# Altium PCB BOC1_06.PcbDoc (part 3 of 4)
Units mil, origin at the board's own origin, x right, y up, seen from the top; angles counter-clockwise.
Board outline 7900 x 6500 mil, 2 copper layers (Top Layer, Bottom Layer); 312 components, 413 nets, 1710 pads, 368 vias.
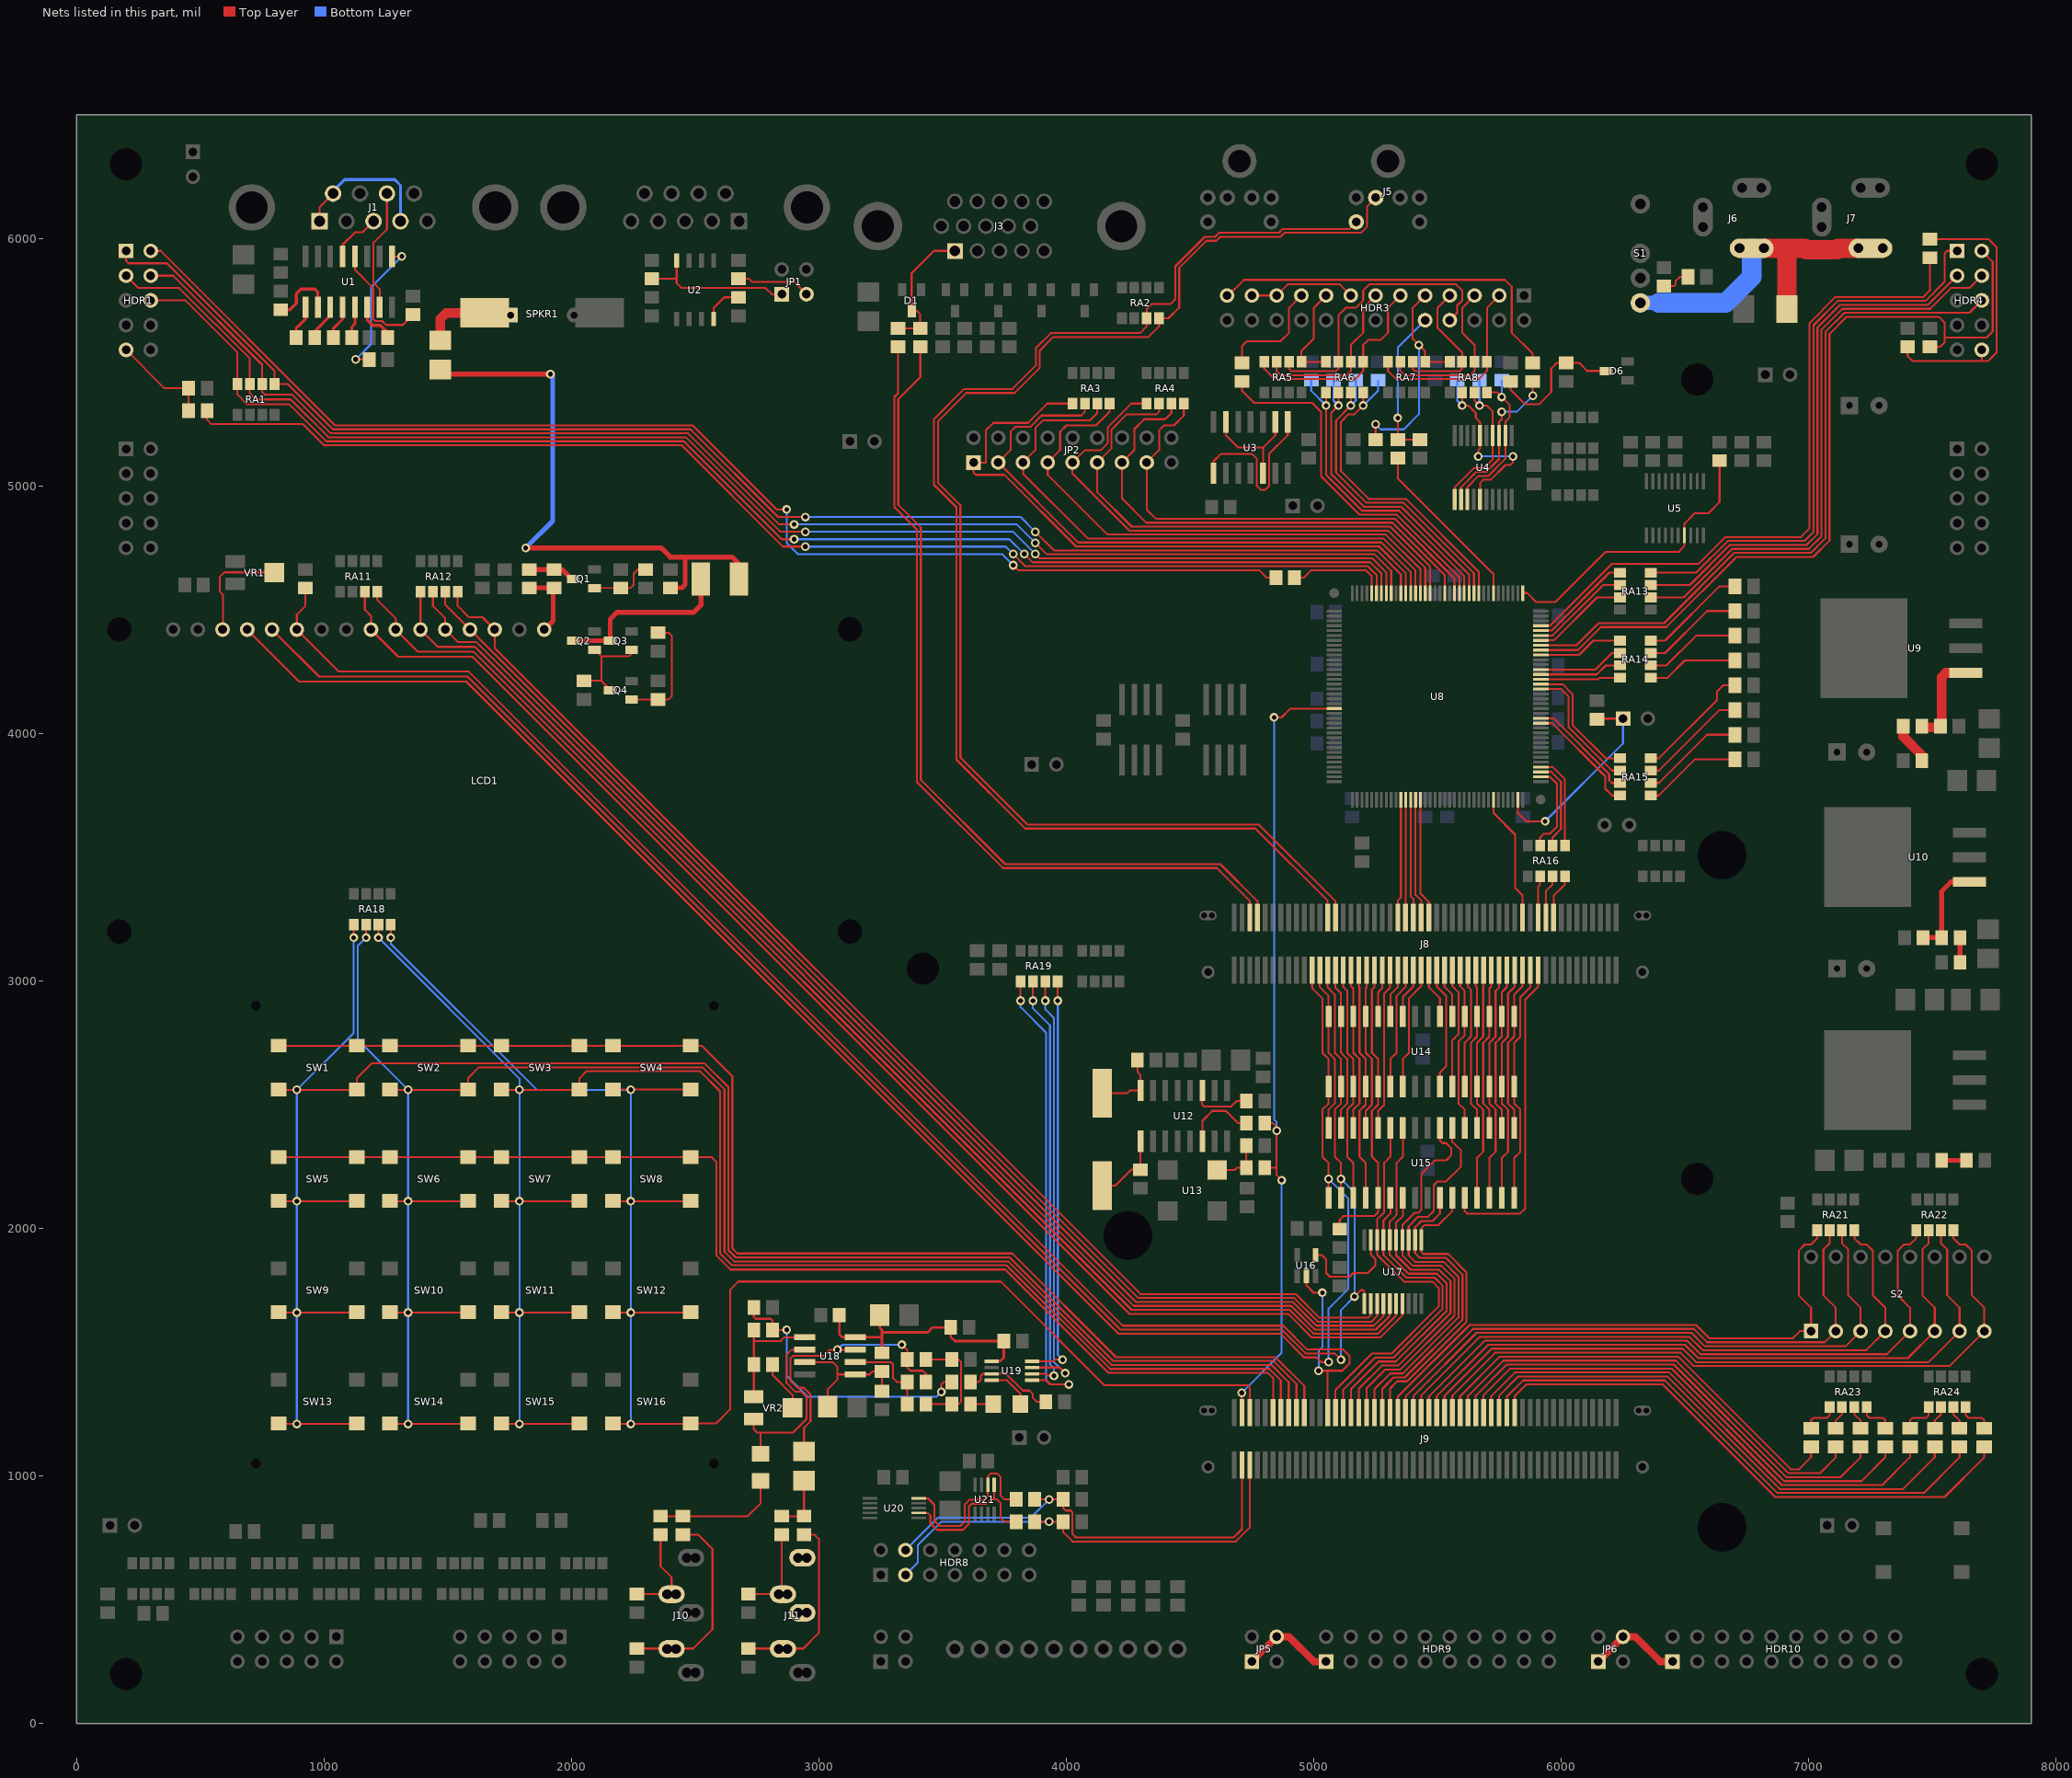
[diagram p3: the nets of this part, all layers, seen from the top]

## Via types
v1: diameter 35.43, hole 19.68, Top Layer to Bottom Layer, 194 vias
v2: diameter 35.43, hole 19.68, Top Layer to Bottom Layer, tented both sides, 169 vias
v3: diameter 50, hole 27.56, Top Layer to Bottom Layer, 5 vias

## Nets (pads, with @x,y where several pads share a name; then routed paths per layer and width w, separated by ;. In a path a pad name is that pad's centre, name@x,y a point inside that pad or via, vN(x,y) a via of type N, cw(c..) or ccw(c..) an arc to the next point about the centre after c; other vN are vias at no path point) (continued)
LCD_D2: LCD1.9 RA11.3 U17.7 | length 5601.5
  Top Layer w7.87: RA11.3@1165,4573 1165,4500 1190,4475 LCD1.9@1190,4420 1300,4310 1600,4310 4255,1655 4896.35,1655 4992.35,1559 5269,1559 5358.39,1648.39 U17.7@5358.39,1696.06
LCD_D3: LCD1.10 RA11.4 U17.6 | length 5483.7
  Top Layer w7.87: RA11.4@1215,4573 1215,4540 1290,4465 LCD1.10@1290,4420 1380,4330 1605,4330 4264,1671 4902.63,1671 4998.63,1575 5260,1575 5332.8,1647.8 U17.6@5332.8,1696.06
LCD_D4: LCD1.11 RA12.1 U17.5 | length 5314.2
  Top Layer w7.87: RA12.1@1390,4573 LCD1.11@1390,4420 1460,4350 1610,4350 4273,1687 4908.9,1687 5004.9,1591 5251,1591 5307.2,1647.2 U17.5@5307.2,1696.06
LCD_D5: LCD1.12 RA12.2 U17.4 | length 5196.4
  Top Layer w7.87: RA12.2@1440,4573 1440,4515 1490,4465 LCD1.12@1490,4420 1540,4370 1615,4370 4282,1703 4915.17,1703 5011.17,1607 5242,1607 5281.61,1646.61 U17.4@5281.61,1696.06
LCD_D6: LCD1.13 RA12.3 U17.3 | length 5078.6
  Top Layer w7.87: RA12.3@1490,4573 1490,4520 4291,1719 4921.44,1719 5017.44,1623 5233,1623 5256.02,1646.02 U17.3@5256.02,1696.06
LCD_D7: LCD1.14 RA12.4 U17.2 | length 5034.6
  Top Layer w7.87: RA12.4@1540,4573 1540,4515 1585,4470 1640,4470 LCD1.14@1690,4420 1690,4345 4300,1735 4927.71,1735 5023.71,1639 5220,1639 5230.43,1649.43 U17.2@5230.43,1696.06
LCD_E: J9.26 LCD1.6 R29.1 U16.2 | length 6425.3
  Top Layer w7.87: R29.1@925,4587.6 925,4515 890,4480 LCD1.6@890,4420 1060,4250 1585,4250 4228,1607 4877.54,1607 4973.54,1511 5119,1511 5145,1485 5145,1455 5115,1425 v2(5020,1425) ; U16.2@4970,1807.68 4970,1770 5000,1740 v1(5035,1740) ; J9.26@5056.3,1256.3 5056.3,1425
  Bottom Layer w7.87: v2(5020,1425) 5020,1505 5035,1520 v1(5035,1740)
LCD_EN: U16.4 U17.19 | length 440.3
  Top Layer w7.87: U16.4@5007.4,1892.32 5032.68,1892.32 5050,1875 5050,1820 5065,1805 5145,1805 5160,1820 5219,1820 5249,1850 5249,1876 5230.43,1894.57 U17.19@5230.43,1953.94
LED0: J9.60 LED0.1 | length 1801
  Top Layer w7.87: J9.60@5591.73,1256.3 5591.73,1321.73 5752,1482 6473,1482 6928,1027 6962,1027 7010,1075 LED0.1@7010,1117.6
LED0#: LED0.2 RA23.1 | length 148.9
  Top Layer w7.87: LED0.2@7010,1192.4 7010,1225 7020,1235 7075,1235 7085,1245 RA23.1@7085,1278
LED1: J9.62 LED1.1 | length 1870.4
  Top Layer w7.87: J9.62@5623.23,1256.3 5623.23,1323.23 5766,1466 6464,1466 6919,1011 7046,1011 7110,1075 LED1.1@7110,1117.6
LED1#: LED1.2 RA23.2 | length 96
  Top Layer w7.87: LED1.2@7110,1192.4 7110,1224 7135,1249 RA23.2@7135,1278
LED2: J9.64 LED2.1 | length 1939.8
  Top Layer w7.87: J9.64@5654.72,1256.3 5654.72,1324.72 5780,1450 6455,1450 6910,995 7130,995 7210,1075 LED2.1@7210,1117.6
LED2#: LED2.2 RA23.3 | length 96
  Top Layer w7.87: RA23.3@7185,1278 7185,1249 7210,1224 LED2.2@7210,1192.4
LED3: J9.66 LED3.1 | length 2009.2
  Top Layer w7.87: J9.66@5686.22,1256.3 5686.22,1326.22 5794,1434 6446,1434 6901,979 7214,979 7310,1075 LED3.1@7310,1117.6
LED3#: LED3.2 RA23.4 | length 148.9
  Top Layer w7.87: RA23.4@7235,1278 7235,1245 7245,1235 7300,1235 7310,1225 LED3.2@7310,1192.4
LED4: J9.68 LED4.1 | length 2075.6
  Top Layer w7.87: J9.68@5717.72,1256.3 5717.72,1322.72 5813,1418 6437,1418 6892,963 7298,963 7410,1075 LED4.1@7410,1117.6
LED4#: LED4.2 RA24.1 | length 148.9
  Top Layer w7.87: LED4.2@7410,1192.4 7410,1225 7420,1235 7475,1235 7485,1245 RA24.1@7485,1278
LED5: J9.70 LED5.1 | length 2145
  Top Layer w7.87: J9.70@5749.21,1256.3 5749.21,1324.21 5827,1402 6428,1402 6883,947 7382,947 7510,1075 LED5.1@7510,1117.6
LED5#: LED5.2 RA24.2 | length 96
  Top Layer w7.87: LED5.2@7510,1192.4 7510,1224 7535,1249 RA24.2@7535,1278
LED6: J9.72 LED6.1 | length 2211.5
  Top Layer w7.87: J9.72@5780.71,1256.3 5780.71,1320.71 5846,1386 6419,1386 6874,931 7466,931 7610,1075 LED6.1@7610,1117.6
LED6#: LED6.2 RA24.3 | length 96
  Top Layer w7.87: RA24.3@7585,1278 7585,1249 7610,1224 LED6.2@7610,1192.4
LED7: J9.74 LED7.1 | length 2280.8
  Top Layer w7.87: J9.74@5812.21,1256.3 5812.2,1322.21 5860,1370 6410,1370 6865,915 7550,915 7710,1075 LED7.1@7710,1117.6
LED7#: LED7.2 RA24.4 | length 148.9
  Top Layer w7.87: RA24.4@7635,1278 7635,1245 7645,1235 7700,1235 7710,1225 LED7.2@7710,1192.4
MASTER: R8.2 U8.103 | length 5097.2
  Top Layer w7.87: R8.2@527.4,5305 527.4,5267.6 545,5250 915,5250 1000,5165 2445,5165 2855,4755 v1(2945,4755) ; v1(3785,4725) 3834,4676 5219,4676 5253.94,4641.06 U8.103@5253.94,4567.32
  Bottom Layer w7.87: v1(2945,4755) 3755,4755 v1(3785,4725)
MASTER#: HDR1.9 R7.2 R8.1 | length 406.8
  Top Layer w7.87: HDR1.9@200,5550 355,5395 R7.2@452.6,5395 R8.1@452.6,5305
MASTER_MODE: HDR1.6 RA1.8 U8.102 | length 5609.4
  Top Layer w7.87: HDR1.6@300,5750 440,5750 650,5540 650,5370 690,5330 860,5330 1009,5181 2454,5181 2850,4785 v1(2900,4785) ; v1(3830,4725) 3863,4692 5228,4692 5273.62,4646.38 U8.102@5273.62,4567.32
  Bottom Layer w7.87: v1(2900,4785) 3770,4785 v1(3830,4725)
MASTER_TCK: HDR1.3 RA1.7 U8.101 | length 5756
  Top Layer w7.87: HDR1.3@200,5850 250,5800 415,5800 700,5515 700,5375 725,5350 865,5350 1018,5197 2463,5197 2845,4815 v1(2945,4815) ; v1(3875,4725) 3892,4708 5237,4708 5293.31,4651.69 U8.101@5293.31,4567.32
  Bottom Layer w7.87: v1(2945,4815) 3785,4815 v1(3875,4725)
MASTER_TDI: HDR1.1 RA1.5 U8.98 | length 5823.7
  Top Layer w7.87: HDR1.1@200,5950 200,5910 210,5900 365,5900 800,5465 RA1.5@800,5412 853,5412 1036,5229 2481,5229 2835,4875 v1(2945,4875) ; v1(3875,4815) 3950,4740 5255,4740 5352.36,4642.64 U8.98@5352.36,4567.32
  Bottom Layer w7.87: v1(2945,4875) 3815,4875 v1(3875,4815)
MASTER_TDO: HDR1.2 R36.1 | length 5173.4
  Top Layer w7.87: HDR1.2@300,5950 340,5950 1045,5245 2490,5245 2830,4905 v1(2870,4905) ; v1(3785,4680) 3805,4660 4780,4660 4810,4630 R36.1@4847.6,4630
  Bottom Layer w7.87: v1(2870,4905) 2870,4770 2915,4725 3740,4725 v1(3785,4680)
MASTER_TDO#: R36.2 U8.104 | length 402.7
  Top Layer w7.87: R36.2@4922.4,4630 4960,4630 4990,4660 5210,4660 5234.25,4635.75 U8.104@5234.25,4567.32
MASTER_TMS: HDR1.4 RA1.6 U8.100 | length 5661.3
  Top Layer w7.87: HDR1.4@300,5850 390,5850 750,5490 750,5380 760,5370 870,5370 1027,5213 2472,5213 2840,4845 v1(2900,4845) ; v1(3875,4770) 3921,4724 5246,4724 5312.99,4657.01 U8.100@5312.99,4567.32
  Bottom Layer w7.87: v1(2900,4845) 3800,4845 v1(3875,4770)
MODE: C85.1 RA6.4 U8.82 | length 1308.8
  Top Layer w7.87: RA6.4@5200,5378 v2(5200,5325) 5165,5290 5140,5290 5110,5260 5110,5060 5222,4948 5372,4948 5667.32,4652.68 U8.82@5667.32,4567.32
  Bottom Layer w7.87: v2(5200,5325) 5260,5385 C85.1@5260,5427.6
MODE_1: JP2.1 RA3.1 U8.97 | length 2611
  Top Layer w7.87: RA3.1@4025,5333 3923,5333 3845,5255 3705,5255 3675,5225 3675,5095 JP2.1@3625,5095 3625,5055 3635,5045 3750,5045 4039,4756 5264,4756 5372.05,4647.95 U8.97@5372.05,4567.32
MODE_2: JP2.3 RA3.2 U8.96 | length 2447.5
  Top Layer w7.87: RA3.2@4075,5333 4075,5300 4060,5285 3900,5285 3854,5239 3794,5239 3775,5220 3775,5145 JP2.3@3725,5095 4048,4772 5273,4772 5391.73,4653.27 U8.96@5391.73,4567.32
MODE_3: JP2.5 RA3.3 U8.95 | length 2358.4
  Top Layer w7.87: RA3.3@4125,5333 4125,5295 4095,5265 3905,5265 3875,5235 3875,5145 JP2.5@3825,5095 3825,5050 4087,4788 5282,4788 5411.42,4658.58 U8.95@5411.42,4567.32
MODE_4: JP2.7 RA3.4 U8.94 | length 2222.4
  Top Layer w7.87: RA3.4@4175,5333 4175,5300 4120,5245 4000,5245 3975,5220 3975,5145 JP2.7@3925,5095 3925,5045 4166,4804 5291,4804 5431.1,4663.9 U8.94@5431.1,4567.32
MODE_5: JP2.9 RA4.1 U8.93 | length 2167.1
  Top Layer w7.87: RA4.1@4325,5333 4263,5333 4167,5237 4167,5172 4140,5145 4075,5145 JP2.9@4025,5095 4025,5050 4255,4820 5300,4820 5450.79,4669.21 U8.93@5450.79,4567.32
MODE_6: JP2.11 RA4.2 U8.92 | length 2109
  Top Layer w7.87: RA4.2@4375,5333 4375,5300 4365,5290 4245,5290 4183,5228 4183,5153 JP2.11@4125,5095 4125,4975 4264,4836 5309,4836 5470.47,4674.53 U8.92@5470.47,4567.32
MODE_7: JP2.13 RA4.3 U8.89 | length 2021.5
  Top Layer w7.87: RA4.3@4425,5333 4425,5295 4400,5270 4315,5270 4275,5230 4275,5145 JP2.13@4225,5095 4225,4950 4323,4852 5318,4852 5529.53,4640.47 U8.89@5529.53,4567.32
MODE_8: JP2.15 RA4.4 U8.87 | length 1931.8
  Top Layer w7.87: RA4.4@4475,5333 4475,5285 4435,5245 4395,5245 4375,5225 4375,5145 JP2.15@4325,5095 4325,4905 4362,4868 5327,4868 5568.9,4626.1 U8.87@5568.9,4567.32
MOUSECLOCK: J5.5 J8.26 RA2.3 | length 5414.9
  Top Layer w7.87: J8.26@5056.3,3256.3 5056.3,3323.7 4764,3616 3834,3616 3556,3894 3556,4914 3465,5005 3465,5270 3587,5392 3782,5392 3877,5487 3877,5557 3938,5618 4298,5618 4325,5645 RA2.3@4325,5678 4325,5715 4345.07,5735.07 4421.07,5735.07 4440.5,5754.5 4440.5,5887.84 4559.66,6007 4600.27,6007 4616.27,6023 4859,6023 4874.75,6038.75 5143.87,6038.75 J5.5@5172.05,6066.93
MOUSEDATA: J5.1 J8.28 RA2.4 | length 5564.2
  Top Layer w7.87: J8.28@5087.79,3256.3 5087.79,3322.21 4778,3632 3843,3632 3572,3903 3572,4923 3481,5014 3481,5261 3596,5376 3791,5376 3893,5478 3893,5548 3947,5602 4332,5602 4375,5645 RA2.4@4375,5678 4413,5678 4456.24,5721.24 4456.24,5881.31 4565.93,5991 4606.54,5991 4622.54,6007 4865.27,6007 4881.27,6023 5190,6023 5216,6049 5216,6130.57 J5.1@5250.79,6165.35
N_TCK: C88.1 RA6.1 U8.85 | length 1257.2
  Top Layer w7.87: RA6.1@5050,5378 5050,5045 5195,4900 5345,4900 5608.27,4636.73 U8.85@5608.27,4567.32
  Bottom Layer w7.87: C88.1@4990,5427.6 4990,5385 v2(5050,5325)
N_TDI: C86.1 RA6.3 U8.83 | length 1265.3
  Top Layer w7.87: RA6.3@5150,5378 v2(5150,5325) 5090,5265 5090,5055 5213,4932 5363,4932 5647.64,4647.36 U8.83@5647.64,4567.32
  Bottom Layer w7.87: v2(5150,5325) 5170,5345 C86.1@5170,5427.6
N_TDO: R16.2 U8.86 | length 1444.7
  Top Layer w7.87: R16.2@4710,5422.6 4710,5385 4759,5336 4994,5336 5030,5300 5030,5040 5186,4884 5336,4884 5588.58,4631.42 U8.86@5588.58,4567.32
N_TDO#: HDR3.10 R16.1 | length 451.1
  Top Layer w7.87: R16.1@4710,5497.4 4710,5565 4730,5585 4865,5585 4900,5620 4900,5720 HDR3.10@4950,5770
N_TMS: C87.1 RA6.2 U8.84 | length 1253
  Top Layer w7.87: RA6.2@5100,5378 v2(5100,5325) 5070,5295 5070,5050 5204,4916 5354,4916 5627.95,4642.05 U8.84@5627.95,4567.32
  Bottom Layer w7.87: C87.1@5080,5427.6 5080,5345 v2(5100,5325)
N_TMS#: HDR3.17 RA5.6 RA6.7 | length 1178.6
  Top Layer w7.87: RA5.6@4900,5502 4900,5474 4910,5464 5090,5464 5100,5474 5100,5690 5130,5720 5170,5720 5200,5750 5200,5790 5225,5815 5575,5815 5600,5790 5600,5750 5580,5730 5580,5700 HDR3.17@5550,5670
NetC3_2: C3.2 U1.2 | length 273.6
  Top Layer w11.81: C3.2@825.1,5712.6 862.6,5712.6 888,5738 888,5777 907,5796 963,5796 975,5784 U1.2@975,5722.64
NetC6_1: C6.1 U1.1 | length 138.1
  Top Layer w11.81: C6.1@887.6,5600 887.6,5637.6 925,5675 U1.1@925,5722.64
NetC6_2: C6.2 U1.3 | length 148.6
  Top Layer w11.81: C6.2@962.4,5600 962.4,5625.1 1025,5687.7 U1.3@1025,5722.64
NetC7_1: C7.1 U1.4 | length 138.1
  Top Layer w11.81: C7.1@1037.6,5600 1037.6,5636.6 1075,5674 U1.4@1075,5722.64
NetC7_2: C7.2 U1.5 | length 127.9
  Top Layer w11.81: C7.2@1112.4,5600 1112.4,5642.4 1125,5655 U1.5@1125,5722.64
NetC8_1: C8.1 U1.6 | length 174.9
  Top Layer w11.81: U1.6@1175,5722.64 1175,5671 1197,5649 1227.95,5649 1257.4,5619.54 C8.1@1257.4,5600
NetC9_1: C9.1 C18.1 L1.2 | length 2315.7
  Top Layer w19.68: C9.1@1470,5470.95 1488.94,5452 v2(1915,5452) ; v2@1815.57,4750 2362.57,4750 2399.57,4713 2648.57,4713 2678.35,4683.23 L1.2@2678.35,4626.57 ; C18.1@2401.48,4588.6 2446.17,4588.6 2459.57,4602 2459.57,4703
  Bottom Layer w19.68: v2@1815.57,4750 1924.6,4859.02 1924.6,5442.4 v2(1915,5452)
  other v2: 1815,4750
NetC9_2: C9.2 SPKR1.1 SPKR1.1A | length 276.6
  Top Layer w39.37: C9.2@1470,5589.06 1470,5675 1494,5700 SPKR1.1@1650,5700
NetC28_1: C28.1 CR1.1 U12.16 | length 287.1
  Top Layer w7.87: CR1.1@4145,2547.01 4247.01,2547.01 4257.36,2557.36 U12.16@4300,2557.36 4300,2620 4287.6,2632.4 C28.1@4287.6,2680
NetC31_1: C31.1 CR1.2 U12.1 | length 296.9
  Top Layer w7.87: CR1.2@4145,2172.99 4197.99,2172.99 4262.4,2237.4 C31.1@4300,2237.4 U12.1@4300,2352.64
NetC36_1: C36.1 R60.2 R67.1 | length 1144
  Top Layer w7.87: C36.1@2737.6,1680 2737.6,1642.4 2745,1635 2805,1635 2812.4,1627.6 R60.2@2812.4,1590 v1(2870,1590) ; v1(3495,1340) 3495,1370 3505,1380 R67.1@3537.6,1380
  Bottom Layer w7.87: v1(2870,1590) 2870,1405 2955,1320 3475,1320 v1(3495,1340)
NetC37_2: C37.2 C38.1 C42.1 R61.2 R63.2 U18.8 U19.1 | length 1079.8
  Top Layer w9.84: C37.2@3082.4,1650 3082.4,1572.6 3095,1560 3255,1560 ; C38.1@3245.95,1650 3245.95,1599.05 3255,1590 R63.2@3255,1497.4 ; 3255,1580 3440,1580 3460,1600 R61.2@3532.6,1600 3532.6,1562.4 3550,1545 C42.1@3747.6,1545 3747.6,1477.6 3733.39,1463.39 U19.1@3698.31,1463.39
NetC39_1: C39.1 R63.1 R65.2 U18.3 U18.5 | length 582.2
  Top Layer w7.87: U18.3@2942.64,1460 3055,1460 3075,1440 3075,1390 3035.95,1350.95 C39.1@3035.95,1280 ; 3075,1410 3205,1410 3217.6,1422.6 R63.1@3255,1422.6 R65.2@3255,1342.4
NetC40_1: C40.1 R66.2 U18.6 | length 365.6
  Top Layer w7.87: U18.6@3147.36,1460 3290,1460 3300,1450 3300,1395 3315,1380 C40.1@3357.6,1380 R66.2@3357.6,1290
NetC40_2: C40.2 C46.1 R64.1 U18.7 | length 1199.7
  Top Layer w7.87: C46.1@2940,1099.05 2940,1195 2966,1221 2966,1329 2939,1356 2914,1356 2885,1385 2885,1475 2895,1485 3020,1485 3045,1510 U18.7@3147.36,1510 ; v1(3335,1530) 3357.6,1507.4 3357.6,1437.4 3370,1425 3420,1425 3432.4,1412.6 C40.2@3432.4,1380
  Bottom Layer w7.87: v1(3075,1510) 3095,1530 v1(3335,1530)
NetC41_1: C41.1 R64.2 R66.1 R68.1 | length 453.5
  Top Layer w7.87: R66.1@3432.4,1290 3565,1290 3575,1300 3575,1460 3565,1470 R64.2@3432.4,1470
NetC43_1: C43.1 R68.2 | length 92.5
  Top Layer w7.87: R68.2@3612.4,1290 C43.1@3704.88,1290
NetC43_2: C43.2 U19.4 | length 180.8
  Top Layer w7.87: U19.4@3698.31,1386.61 3759.39,1386.61 3815.12,1330.88 C43.2@3815.12,1290
NetC44_1: C44.1 R67.2 U19.3 | length 382.6
  Top Layer w7.87: R67.2@3612.4,1380 3645,1380 3655,1390 3655,1405 3662.2,1412.2 3756.8,1412.2 3824,1345 3850,1345 3865,1330 3865,1315 3880,1300 C44.1@3917.6,1300
NetC45_1: C45.1 R71.2 R72.2 | length 516.7
  Top Layer w7.87: R71.2@2360,837.4 2712.4,837.4 2765,890 C45.1@2765,979.88
NetC45_2: C45.2 U18.2 VR2.CCW | length 757.6
  Top Layer w7.87: VR2.CCW@2736.26,1229.72 2736.26,1188.74 2750,1175 2895,1175 2950,1230 2950,1320 2930,1340 2905,1340 2869,1376 2869,1489 2890,1510 U18.2@2942.64,1510 ; C45.2@2765,1090.12 2765,1175
NetC46_2: C46.2 R73.2 R74.2 | length 233.5
  Top Layer w7.87: R73.2@2850,837.4 R74.2@2940,837.4 C46.2@2940,980.94
NetC50_1: C50.1 J10.4 J10.4A J10.4B R71.1 | length 398.4
  Top Layer w7.87: C50.1@2265,522.4 2404.72,522.4 2404.72,590.28 2360,635 R71.1@2360,762.6
NetC51_1: C51.1 J10.2 J10.2A J10.2B R72.1 | length 806.1
  Top Layer w7.87: C51.1@2265,302.4 2492.6,302.4 2570,380 2570,705 2512.4,762.6 R72.1@2450,762.6
NetC52_1: C52.1 J11.4 J11.4A J11.4B R73.1 | length 375.2
  Top Layer w7.87: C52.1@2715,522.4 2850,522.4 R73.1@2850,762.6
NetC53_1: C53.1 J11.2 J11.2A J11.2B R74.1 | length 758.2
  Top Layer w7.87: C53.1@2715,302.4 2937.4,302.4 3000,365 3000,745 2982.4,762.6 R74.1@2940,762.6
NetD6_3: D6.3 R17.2 R19.1 | length 582.6
  Top Layer w7.87: R17.2@5795,5422.6 5795,5390 5855,5330 5910,5330 5960,5380 5960,5475 5982.4,5497.4 6072.6,5497.4 6105,5465 D6.3@6181.69,5465
NetJ1_1: J1.1 J1.4 J1.6 | length 590.3
  Top Layer w7.87: J1.1@981.89,6070.08 981.89,6127.36 J1.6@1036.42,6181.89
  Bottom Layer w11.81: J1.6@1036.42,6181.89 1036.42,6191.42 1083,6238 1286,6238 1309.05,6214.95 J1.4@1309.05,6070.08
NetJ11_3: J11.3 J11.3A J11.3B
NetJ11_5: J11.5 J11.5A J11.5B
NetJP1_1: JP1.1 R2.2 U2.8 | length 634.9
  Top Layer w7.87: R2.2@2325,5837.6 2425,5837.6 ; U2.8@2425,5911.22 2425,5820 2445,5800 2785,5800 2810,5775 JP1.1@2850,5775
NetJP1_3: JP1.3 R3.1 | length 300.9
  Top Layer w7.87: R3.1@2675,5837.6 2717.4,5837.6 2730,5825 2900,5825 JP1.3@2950,5775
NetL1_1: L1.1 Q2.3 Q3.3 | length 733.4
  Top Layer w19.68: Q2.3@2006.69,4375 Q3.3@2156.69,4375 2156.69,4461.69 2185,4490 2495,4490 2523.23,4518.23 L1.1@2523.23,4625
NetLCD1_3: LCD1.3 VR1.W | length 446.8
  Top Layer w7.87: LCD1.3@591.53,4419.9 591.53,4561 578.23,4574.31 578.23,4632.65 596.85,4651.28 VR1.W@799.06,4651.28
NetLCD1_16: LCD1.16 R32.1 R33.1 | length 283.2
  Top Layer w19.68: R32.1@1826.47,4588.6 1926.47,4588.6 1926.47,4454.84 LCD1.16@1891.54,4419.9
NetLED8_1: LED8.1 R5.2 | length 120.7
  Top Layer w7.87: R5.2@6415,5807.6 6455.6,5807.6 6462,5814 6462,5827 6480,5845 LED8.1@6512.6,5845
NetQ1_1: Q1.1 R34.2 R35.2 | length 265.5
  Top Layer w7.87: Q1.1@2093.31,4587.6 2239.17,4588.6 2251.57,4601 2251.57,4646 2268.97,4663.4 R35.2@2301.48,4663.4
NetQ1_3: Q1.3 R32.2 R33.2 | length 184.1
  Top Layer w19.68: R32.2@1830,4662.4 R33.2@1930,4662.4 1961.17,4663.4 Q1.3@1998.57,4626
NetQ2_1: Q2.1 Q3.1 Q4.3 R38.2 | length 387.1
  Top Layer w7.87: R38.2@2051.47,4213.4 2120.87,4213.4 ; Q2.1@2094.88,4338.6 2120.87,4312.61 ; Q4.3@2158.27,4176 2120.87,4213.4 ; Q3.1@2244.88,4324.31 2233.19,4312.61 2120.87,4312.61 ; 2120.87,4213.4 2120.87,4312.61
NetQ4_1: Q4.1 R37.2 R39.1 | length 472
  Top Layer w7.87: Q4.1@2243.31,4137.6 2392.6,4137.6 2405,4150 2405,4395 2392.6,4407.4 R37.2@2350,4407.4
NetR1_2: R1.2 U1.12 | length 471.3
  Top Layer w7.87: U1.12@1125,5927.36 1125,5873.73 1198.62,5800.11 1198.62,5675.38 1207,5667 1235,5667 1251,5651 1318.5,5651 R1.2@1360.1,5692.6
NetR4_2: R4.2 U2.4 | length 162.6
  Top Layer w7.87: U2.4@2575,5675 2575,5720 2617.4,5762.4 R4.2@2675,5762.4
NetR9_2: R9.2 U1.9 | length 584.8
  Top Layer w7.87: v2(1128,5512) R9.2@1180.5,5512 ; U1.9@1275,5927.36 v2(1314.64,5927.36)
  Bottom Layer w7.87: v2(1128,5512) 1190,5574 1190,5802.73 v2(1314.64,5927.36)
NetR41_1: R41.1 R42.2 U9.1 | length 377.5
  Top Layer w39.37: R41.1@7457.4,4024.9 R42.2@7532.6,4024.9 ; R42.2@7537.6,4029.9 7537.6,4227.6 7555,4245 U9.1@7635,4245
NetR41_2: R41.2 R43.1 | length 173.1
  Top Layer w39.37: R41.2@7382.6,4030 7382.6,3987.4 7460,3910 7460,3892.6 R43.1@7457.4,3890
NetR47_2: R47.2 R48.1 U10.1 | length 390.6
  Top Layer w19.68: R47.2@7462.4,3175.1 7537.6,3175.1 7537.6,3362.6 7575,3400 U10.1@7650,3400
NetR48_2: R48.2 R49.2 | length 100
  Top Layer w19.68: R49.2@7612.4,3075 R48.2@7612.4,3175
NetR51_1: R51.1 U12.11 | length 247
  Top Layer w7.87: U12.11@4549,2557.36 4549,2500 4556,2493 4667,2493 4689.1,2515.1 R51.1@4726.6,2515.1
NetR52_1: R52.1 U12.6 | length 297.2
  Top Layer w7.87: U12.6@4550,2352.64 4550,2435 4590,2475 4645,2475 4695,2425 R52.1@4727.6,2425
NetR53_1: R53.1 R54.1 U13.3 | length 210.3
  Top Layer w7.87: U13.3@4610,2236.1 4680.1,2236.1 4689.1,2245.1 4726.6,2245.1 R53.1@4726.6,2335.1
NetR57_2: R57.2 R58.1 | length 100.2
  Top Layer w19.68: R57.2@7537.4,2275.1 R58.1@7637.6,2275.1
NetR60_1: R60.1 R62.2 U18.1 VR2.CW | length 481.3
  Top Layer w7.87: VR2.CW@2737.6,1320 R60.1@2737.6,1590 ; 2737.6,1545 2845,1545 2860,1560 U18.1@2942.64,1560
NetR62_1: R62.1 VR2.W | length 208.7
  Top Layer w7.87: R62.1@2812.4,1450 2812.4,1407.6 2893.74,1326.26 VR2.W@2893.74,1275
NetRA19_1: RA19.1 U19.5 | length 1907.9
  Top Layer w7.87: v1(3815,2920) RA19.1@3815,2998 ; U19.5@3861.69,1386.61 3918.39,1386.61 3935,1370 v1(4010,1370)
  Bottom Layer w7.87: v1(3815,2920) 3815,2895 3918.5,2791.5 3918.5,1386.5 3935,1370 v1(4010,1370)
NetRA19_2: RA19.2 U19.6 | length 1729.5
  Top Layer w7.87: U19.6@3861.69,1412.2 3917.8,1412.2 3925,1405 v1(3950,1405) ; v1@3865,2910 RA19.2@3865,2998
  Bottom Layer w7.87: v1(3865,2920) 3865,2890 3934.25,2820.75 3934.25,1450.75 3950,1435 v1(3950,1405)
NetRA19_3: RA19.3 U19.7 | length 1758.9
  Top Layer w7.87: U19.7@3861.69,1437.8 3972.2,1437.8 v1(3995,1415) ; v1(3915,2920) RA19.3@3915,2998
  Bottom Layer w7.87: v1(3915,2920) 3915,2885 3950,2850 3950,1460 v1(3995,1415)
NetRA19_4: RA19.4 U19.8 | length 1662.3
  Top Layer w7.87: U19.8@3861.69,1463.39 3948.39,1463.39 3955,1470 v1(3985,1470) ; v1(3965,2920) RA19.4@3965,2998
  Bottom Layer w7.87: v1(3965,2920) 3965.75,2919.25 3965.75,1489.25 v1(3985,1470)
NetU3_1: U3.1 U3.8 | length 705.9
  Top Layer w7.87: U3.8@4595,5051.65 4595,5100 4625,5130 4750,5130 4770,5110 4770,5000 4785,4985 4805,4985 4820,5000 4820,5130 4895,5205 U3.1@4895,5258.35
NetU3_2: U3.2 U3.6 U3.12 | length 451.5
  Top Layer w7.87: U3.6@4645,5258.35 4645,5205 4695,5155 4795,5155 ; U3.12@4795,5051.65 4795,5155 ; U3.2@4845,5258.35 4845,5205 4795,5155
NEXUS_TCK: J8.82 RA16.3 | length 177.8
  Top Layer w7.87: J8.82@5938.19,3256.3 5938.19,3363.19 5965,3390 RA16.3@5965,3423
NEXUS_TCK#: RA16.6 U8.39 | length 370.9
  Top Layer w7.87: U8.39@5917.32,3844.88 5960.12,3844.88 5999,3806 5999,3614 5965,3580 RA16.6@5965,3547
NEXUS_TDI: J8.84 RA16.4 | length 185.5
  Top Layer w7.87: J8.84@5969.69,3256.3 5969.69,3344.69 6015,3390 RA16.4@6015,3423
NEXUS_TDI#: RA16.5 U8.40 | length 386.2
  Top Layer w7.87: U8.40@5917.32,3864.57 5965.43,3864.57 6015,3815 RA16.5@6015,3547
NEXUS_TDO: J8.76 U8.30 | length 525
  Top Layer w7.87: U8.30@5726.38,3732.68 5726.38,3678.62 5814,3591 5814,3376 5843.7,3346.3 J8.76@5843.7,3256.3
NEXUS_TMS: J8.80 RA16.2 | length 170.1
  Top Layer w7.87: J8.80@5906.69,3256.3 5906.69,3381.69 5915,3390 RA16.2@5915,3423
NEXUS_TMS#: RA16.7 U8.38 | length 370.2
  Top Layer w7.87: RA16.7@5915,3547 5915,3580 5930,3595 5955,3595 5983,3623 5983,3797 5954.8,3825.2 U8.38@5917.32,3825.2
PAR_TCK: C82.1 RA8.3 U4.4 U4.11 | length 669.5
  Top Layer w7.87: U4.11@5569.84,4946.06 5569.84,4994.84 5648,5073 5688,5073 5723.39,5108.39 5723.39,5301.61 5700,5325 v2(5670,5325) 5650,5345 RA8.3@5650,5378
  Bottom Layer w7.87: v2(5670,5325) C82.1@5670,5427.6
PAR_TDI: C81.1 RA8.4 U4.2 U4.13 | length 656.5
  Top Layer w7.87: U4.13@5621.02,4946.06 5621.02,4996.02 5666,5041 5706,5041 5774.57,5109.57 5774.57,5259.57 5792,5277 5792,5328 5742,5378 RA8.4@5700,5378
  Bottom Layer w7.87: v2(5760,5360) C81.1@5760,5427.6
PAR_TDO: R18.2 U4.3 U4.12 | length 655.1
  Top Layer w7.87: U4.12@5595.43,4946.06 5595.43,4995.43 5657,5057 5697,5057 5748.98,5108.98 5748.98,5258.98 5760,5270 v2(5760,5300) ; v2(5885,5365) R18.2@5885,5422.6
  Bottom Layer w7.87: v2(5760,5300) 5820,5300 v2(5885,5365)
PAR_TDO#: HDR3.13 R18.1 | length 1532.6
  Top Layer w7.87: HDR3.13@4650,5765 4718,5833 5772,5833 5800,5805 5800,5620 5885,5535 R18.1@5885,5497.4
PAR_TMS: C83.1 RA8.2 U4.6 U4.15 | length 814.7
  Top Layer w7.87: RA8.2@5600,5378 v2(5600,5325) 5625,5325 5655,5295 5655,5275 5672.2,5257.8 5672.2,5152.2 5665,5145 v2(5665,5120) ; U4.15@5672.2,4946.06 5672.2,5012.2 5685,5025 5715,5025 5775,5085 5795,5085 5805,5095 v2(5805,5120)
  Bottom Layer w7.87: C83.1@5580,5427.6 5580,5345 v2(5600,5325) ; v2(5665,5120) v2(5805,5120)
PARALLEL: R23.2 U8.79 | length 705.3
  Top Layer w7.87: R23.2@5340,5112.6 5340,5030 5726.38,4643.62 U8.79@5726.38,4567.32
PARALLEL#: HDR3.18 R23.1 R24.1 | length 613.2
  Top Layer w7.87: v2@5340,5270 R23.1@5340,5187.4 R24.1@5430,5187.4
  Bottom Layer w7.87: v2(5340,5275) 5340,5560 HDR3.18@5450,5670
PROGRAM: R25.2 U5.7 U8.73 | length 1195.8
  Top Layer w7.87: U8.73@5844.49,4567.32 5862.68,4567.32 5899,4531 5976,4531 6179,4734 6474,4734 6498.39,4758.39 6498.39,4848.39 6540,4890 6595,4890 6640,4935 R25.2@6640,5100.2
PU0: HDR3.2 RA7.8 RA8.5 | length 790
  Top Layer w7.87: RA7.8@5300,5502 5300,5465 5333,5432 5667,5432 5700,5465 5700,5720 HDR3.2@5750,5770
PU1: HDR3.3 RA7.7 RA8.6 | length 697.5
  Top Layer w7.87: RA7.7@5350,5502 5350,5465 5367,5448 5633,5448 5650,5465 5650,5570 5600,5620 5600,5720 HDR3.3@5650,5770
PU2: HDR3.4 RA7.6 RA8.7 | length 594.4
  Top Layer w7.87: RA7.6@5400,5502 5400,5474 5410,5464 5590,5464 5600,5474 5600,5540 5500,5640 5500,5720 HDR3.4@5550,5770
PU3: HDR3.5 R22.1 RA7.5 RA8.8 | length 961
  Top Layer w7.87: R22.1@5250,5187.4 v2(5250,5250) ; HDR3.5@5450,5770 5400,5720 5400,5595 5450,5545 RA7.5@5450,5502 RA8.8@5550,5502
  Bottom Layer w7.87: v2(5250,5250) 5271,5229 5364,5229 5425,5290 v2(5425,5570)
PU4: HDR3.6 RA5.8 RA6.5 | length 855.5
  Top Layer w7.87: RA5.8@4800,5502 4800,5474 4842,5432 5167,5432 5200,5465 5200,5570 5220,5590 5270,5590 5300,5620 5300,5720 HDR3.6@5350,5770
PU5: HDR3.7 RA5.7 RA6.6 | length 697.5
  Top Layer w7.87: RA5.7@4850,5502 4850,5465 4867,5448 5133,5448 5150,5465 5150,5570 5200,5620 5200,5720 HDR3.7@5250,5770
PU6#: HDR3.8 HDR3.11 HDR3.12 | length 437.3
  Top Layer w7.87: HDR3.12@4750,5770 HDR3.11@4850,5770 4895,5815 5105,5815 HDR3.8@5150,5770
PU7: HDR3.9 RA5.5 RA6.8 | length 409.4
  Top Layer w7.87: RA6.8@5050,5502 RA5.5@4950,5502 4950,5545 5000,5595 5000,5720 HDR3.9@5050,5770
PWR_IN: D7.2 J6.1 J6.1A J6.1B J7.1 J7.1A J7.1B S1.3 | length 1241
  Top Layer w78.74: J6.1B@6819.21,5960.63 6984.37,5960.63 6990,5955 7115,5955 7120.63,5960.63 J7.1A@7200.79,5960.63 ; D7.2@6912.5,5715 6912.5,5960.63
  Bottom Layer w59.06: S1.3@6320,5740 6395,5740
  Bottom Layer w78.74: 6395,5740 6665,5740 6770,5845 J6.1@6770,5960.63
PWR_USER_1: HDR9.1 JP5.1 JP5.4 | length 382.8
  Top Layer w29.53: JP5.1@4750,250 JP5.4@4850,350 4900,350 5000,250 HDR9.1@5050,250
PWR_USER_2: HDR10.1 JP6.1 JP6.4 | length 382.8
  Top Layer w29.53: JP6.1@6150,250 JP6.4@6250,350 6300,350 6400,250 HDR10.1@6450,250
RAM0_DATA0: J9.42 U15.11 U17.11 | length 1236.7
  Top Layer w7.87: J9.42@5308.27,1256.3 5308.27,1353.27 5337,1382 5377,1382 5617,1622 5617,1823 5543,1897 5443,1897 5435.16,1904.84 5435.16,2001.16 5447,2013 5503,2013 5560,2070 U15.11@5560,2123.27
RAM0_DATA1: J9.40 U15.10 U17.12 | length 1236.4
  Top Layer w7.87: J9.40@5276.77,1256.3 5276.77,1351.77 5323,1398 5368,1398 5601,1631 5601,1814 5534,1881 5429,1881 5409.57,1900.43 5409.57,2004.57 5435,2030 5480,2030 5510,2060 U15.10@5510,2123.27
RAM0_DATA2: J9.38 U15.22 U17.13 | length 1616.9
  Top Layer w7.87: J9.38@5245.28,1256.3 5245.28,1350.28 5309,1414 5359,1414 5585,1640 5585,1805 5525,1865 5410,1865 5383.98,1891.02 5383.98,2008.98 5422,2047 5462,2047 5485,2070 5485,2175 5500,2190 5535,2190 5595,2250 5595,2315 5560,2350 U15.22@5560,2406.73
RAM0_DATA3: J9.36 U15.23 U17.14 | length 1631.3
  Top Layer w7.87: J9.36@5213.78,1256.3 5213.78,1353.78 5290,1430 5350,1430 5569,1649 5569,1796 5516,1849 5401,1849 5358.39,1891.61 5358.39,2013.39 5409,2064 5424,2064 5435,2075 5435,2220 5490,2275 5535,2275 5555,2295 5555,2325 5535,2345 5520,2345 5510,2355 U15.23@5510,2406.73
RAM0_DATA4: J9.34 U15.7 U17.15 | length 1228.4
  Top Layer w7.87: J9.34@5182.28,1256.3 5182.28,1352.28 5276,1446 5341,1446 5553,1658 5553,1787 5507,1833 5392,1833 5332.8,1892.2 5332.8,2022.8 5360,2050 U15.7@5360,2123.27
RAM0_DATA5: J9.32 U15.26 U17.16 | length 1535.8
  Top Layer w7.87: J9.32@5150.79,1256.3 5150.79,1350.79 5262,1462 5332,1462 5537,1667 5537,1778 5498,1817 5383,1817 5307.2,1892.8 5307.2,2027.2 5335,2055 5335,2265 5360,2290 U15.26@5360,2406.73
RAM0_DATA6: J9.30 U15.6 U17.17 | length 1255.6
  Top Layer w7.87: J9.30@5119.29,1256.3 5119.29,1349.29 5248,1478 5323,1478 5521,1676 5521,1769 5489,1801 5374,1801 5281.61,1893.39 5281.61,2031.61 5310,2060 U15.6@5310,2123.27
RAM0_DATA7: J9.28 U15.27 U17.18 | length 1563
  Top Layer w7.87: J9.28@5087.79,1256.3 5087.79,1347.79 5234,1494 5314,1494 5505,1685 5505,1760 5480,1785 5365,1785 5256.02,1893.98 5256.02,2036.02 5285,2065 5285,2265 5310,2290 U15.27@5310,2406.73
RAM0_OE: J8.41 U15.28 | length 657
  Top Layer w7.87: U15.28@5260,2406.73 5260,2475 5285,2500 5285,2950 5308.27,2973.27 J8.41@5308.27,3043.7
RAM0_WE: J8.79 U15.12 | length 1295.2
  Top Layer w7.87: U15.12@5610,2123.27 5610,2070 5620,2060 5834,2060 5855,2081 5855,2925 5906.69,2976.69 J8.79@5906.69,3043.7
RAM1_DATA0: J8.45 U14.6 | length 495.8
  Top Layer w7.87: U14.6@5310,2573.27 5310,2685 5335,2710 5335,2940 5371.26,2976.26 J8.45@5371.26,3043.7
RAM1_DATA1: J8.49 U14.7 | length 501.2
  Top Layer w7.87: U14.7@5360,2573.27 5360,2685 5385,2710 5385,2930 5434.25,2979.25 J8.49@5434.25,3043.7
RAM1_DATA2: J8.53 U14.10 | length 496.4
  Top Layer w7.87: J8.53@5497.24,3043.7 5497.24,2977.76 5535,2940 5535,2655 5510,2630 U14.10@5510,2573.27
RAM1_DATA3: J8.57 U14.11 | length 491
  Top Layer w7.87: U14.11@5560,2573.27 5560,2760 5585,2785 5585,2955 5560.24,2979.76 J8.57@5560.24,3043.7
RAM1_DATA4: J8.55 U14.22 | length 199.9
  Top Layer w7.87: J8.55@5528.74,3043.7 5528.74,2976.26 5560,2945 U14.22@5560,2856.73
RAM1_DATA5: J8.51 U14.23 | length 205.3
  Top Layer w7.87: J8.51@5465.75,3043.7 5465.75,2974.25 5510,2930 U14.23@5510,2856.73
RAM1_DATA6: J8.47 U14.26 | length 204.7
  Top Layer w7.87: U14.26@5360,2856.73 5360,2935 5402.76,2977.76 J8.47@5402.76,3043.7
RAM1_DATA7: J8.43 U14.27 | length 199.3
  Top Layer w7.87: U14.27@5310,2856.73 5310,2945 5339.76,2974.76 J8.43@5339.76,3043.7
RAM1_OE: J8.39 U14.28 | length 193.9
  Top Layer w7.87: U14.28@5260,2856.73 5260,2955 5276.77,2971.77 J8.39@5276.77,3043.7
RAM1_WE: J8.61 U14.12 | length 485.7
  Top Layer w7.87: U14.12@5610,2573.27 5610,2750 5635,2775 5635,2965 5623.23,2976.77 J8.61@5623.23,3043.7
RAM_ADDR0: J8.21 LCD1.4 U14.1 U15.1 | length 7371.1
  Top Layer w7.87: LCD1.4@690,4420 900,4210 1575,4210 4210,1575 4865,1575 4961,1479 5011,1479 5030,1460 v2(5060,1460) ; J8.21@4993.31,3043.7 4993.31,2971.69 5035,2930 5035,2710 5060,2685 5060,2505 5035,2480 5035,2290 5060,2265 U15.1@5060,2123.27
  Bottom Layer w7.87: v2(5060,1460) 5060,1676 5140,1756 5140,2120 v2(5060,2200)
RAM_ADDR1: J8.25 LCD1.5 U14.2 U15.2 U17.1 | length 7382.2
  Top Layer w7.87: LCD1.5@790,4420 980,4230 1580,4230 4219,1591 4871.27,1591 4967.27,1495 5085,1495 v2(5110,1470) ; J8.25@5056.3,3043.7 5056.3,2973.7 5085,2945 5085,2710 5110,2685 5110,2505 5085,2480 5085,2290 5110,2265 U15.2@5110,2123.27 ; v2(5165,1725) 5190,1750 5200,1750 5204.84,1745.16 U17.1@5204.84,1696.06
  Bottom Layer w7.87: v2(5110,1470) 5110,1670 v2(5165,1725) 5165,2145 v2(5110,2200)
RAM_ADDR2: J8.29 U14.3 U15.3 | length 958
  Top Layer w7.87: J8.29@5119.29,3043.7 5119.29,2975.71 5135,2960 5135,2710 5160,2685 5160,2505 5135,2480 5135,2290 5160,2265 U15.3@5160,2123.27
RAM_ADDR3: J8.33 U14.4 U15.4 | length 952.6
  Top Layer w7.87: J8.33@5182.28,3043.7 5182.28,2977.72 5185,2975 5185,2710 5210,2685 5210,2500 5185,2475 5185,2290 5210,2265 U15.4@5210,2123.27
RAM_ADDR4: J8.65 U14.13 U15.13 | length 952
  Top Layer w7.87: U15.13@5660,2123.27 5660,2285 5685,2310 5685,2480 5660,2505 5660,2750 5685,2775 5685,2975 5686.22,2976.22 J8.65@5686.22,3043.7
RAM_ADDR5: J8.69 U14.14 U15.14 | length 957.4
  Top Layer w7.87: U15.14@5710,2123.27 5710,2285 5735,2310 5735,2480 5710,2505 5710,2750 5735,2775 5735,2960 5749.21,2974.21 J8.69@5749.21,3043.7
RAM_ADDR6: J8.73 U14.15 U15.15 | length 962.8
  Top Layer w7.87: U15.15@5760,2123.27 5760,2285 5785,2310 5785,2480 5760,2505 5760,2750 5785,2775 5785,2950 5812.2,2977.21 J8.73@5812.21,3043.7
RAM_ADDR7: J8.77 U14.16 U15.16 | length 968.1
  Top Layer w7.87: U15.16@5810,2123.27 5810,2285 5835,2310 5835,2480 5810,2505 5810,2750 5835,2775 5835,2935 5875.2,2975.2 J8.77@5875.2,3043.7
RAM_ADDR8: J8.75 U14.17 U15.17 | length 671.6
  Top Layer w7.87: U15.17@5810,2406.73 5810,2480 5785,2505 5785,2750 5810,2775 5810,2945 5843.7,2978.7 J8.75@5843.7,3043.7
RAM_ADDR9: J8.71 U14.18 U15.18 | length 666.3
  Top Layer w7.87: U15.18@5760,2406.73 5760,2480 5735,2505 5735,2750 5760,2775 5760,2955 5780.71,2975.71 J8.71@5780.71,3043.7
RAM_ADDR10: J8.67 U14.19 U15.19 | length 660.9
  Top Layer w7.87: U15.19@5710,2406.73 5710,2480 5685,2505 5685,2750 5710,2775 5710,2970 5717.72,2977.72 J8.67@5717.72,3043.7
RAM_ADDR11: J8.63 U14.20 U15.20 | length 659.9
  Top Layer w7.87: J8.63@5654.72,3043.7 5654.72,2980.28 5660,2975 5660,2775 5635,2750 5635,2505 5660,2480 U15.20@5660,2406.73
RAM_ADDR12: J8.59 U14.21 U15.21 | length 665.2
  Top Layer w7.87: J8.59@5591.73,3043.7 5591.73,2978.27 5610,2960 5610,2780 5585,2755 5585,2505 5610,2480 U15.21@5610,2406.73
RAM_ADDR13: J8.35 U14.29 U15.29 | length 659.2
  Top Layer w7.87: U15.29@5210,2406.73 5210,2475 5235,2500 5235,2685 5210,2710 5210,2970 5213.78,2973.78 J8.35@5213.78,3043.7
RAM_ADDR14: J8.31 U14.30 U15.30 | length 661.5
  Top Layer w7.87: J8.31@5150.79,3043.7 5150.79,2979.21 5160,2970 5160,2710 5185,2685 5185,2505 5160,2480 U15.30@5160,2406.73
RAM_ADDR15: J8.27 U14.31 U15.31 | length 666.9
  Top Layer w7.87: J8.27@5087.79,3043.7 5087.79,2972.21 5110,2950 5110,2710 5135,2685 5135,2505 5110,2480 U15.31@5110,2406.73
RAM_ADDR16: J8.23 U14.32 U15.32 | length 672.3
  Top Layer w7.87: J8.23@5024.8,3043.7 5024.8,2975.2 5060,2940 5060,2710 5085,2685 5085,2505 5060,2480 U15.32@5060,2406.73
RAM_CS: J8.37 R59.2 U14.5 U15.5 | length 1219
  Top Layer w7.87: R59.2@5105,1997.4 5105,2035 5120,2050 5245,2050 5260,2065 5260,2265 5235,2290 5235,2475 5260,2500 5260,2685 5235,2710 5235,2965 5245.28,2975.28 J8.37@5245.28,3043.7
RED0: J8.6 R10.1 | length 3414.2
  Top Layer w7.87: R10.1@3320,5562.6 3320,5375 3305,5360 3305,4915 3396,4824 3396,3804 3744,3456 4609,3456 4741.34,3323.66 J8.6@4741.34,3256.3
RED1: J8.8 R11.1 | length 3454.2
  Top Layer w7.87: R11.1@3410,5562.6 3410,5440 3321,5351 3321,4924 3412,4833 3412,3813 3753,3472 4623,3472 4772.83,3322.17 J8.8@4772.83,3256.3
RED#: D1.3 J3.1 R10.2 R11.2 | length 552.4
  Top Layer w7.87: R10.2@3319.9,5637.4 3409.9,5637.4 3409.9,5694.1 3397.31,5706.69 D1.3@3375,5706.69 3375,5860 3465,5950 J3.1@3550,5950
REF_CLK: J9.4 R52.2 R54.2 U8.129 | length 3262.1
  Top Layer w7.87: v1(4709,1336) 4709,1257.14 J9.4@4709.84,1256.3 ; R54.2@4802.4,2245 4850,2245 ; R52.2@4802.4,2425 4835,2425 4850,2410 4850,2215 v2(4870,2195) ; v1(4840,4065) 4870,4065 4905.79,4100.79 U8.129@5082.68,4100.79
  Bottom Layer w7.87: v1(4709,1336) 4870,1497 v2(4870,2195) ; v1(4840,4065) 4840,2440 4850,2430 v1(4850,2395)
RTS: J1.8 U1.7 | length 492.2
  Top Layer w7.87: U1.7@1225,5722.64 1225,5796 1200,5821 1200,5983 1254.53,6037.53 J1.8@1254.53,6181.89
RX: J1.3 U1.13 | length 212
  Top Layer w7.87: U1.13@1075,5927.36 1075,5975 1125,6025 1154.92,6025 J1.3@1200,6070.08
SCL: HDR8.3 J9.5 R78.1 R79.2 | length 1912.8
  Top Layer w7.87: R78.1@3872.4,815 R79.2@3987.6,815 3987.6,772.4 4025,735 4685,735 4741.34,791.34 J9.5@4741.34,1043.7
  Bottom Layer w7.87: HDR8.3@3350,600 3400,650 3400,720 3495,815 v1(3930,815)
SCL#: R78.2 U20.2 U21.5 | length 663.5
  Top Layer w7.87: U20.2@3403.43,850.31 3439.69,850.31 3451,839 3451,809 3478,782 3582,782 3606,806 3606,876 3618,888 3678,888 3695,905 3720,905 3735,890 3735,830 3750,815 R78.2@3797.6,815 ; 3708.39,905 U21.5@3708.39,964.06
SDA: HDR8.4 J9.3 R76.1 R77.2 | length 1910.8
  Top Layer w7.87: R76.1@3872.4,905 R77.2@3987.6,905 3987.6,870.4 3998,860 4018,860 4025,853 4025,765 4039,751 4676,751 4709.84,784.84 J9.3@4709.84,1043.7
  Bottom Layer w7.87: HDR8.4@3350,700 3481,831 3856,831 v1(3930,905)
SDA#: R76.2 U20.5 U21.6 | length 741.5
  Top Layer w7.87: U20.5@3403.43,909.37 3440.63,909.37 3467,883 3467,818 3487,798 3573,798 3590,815 3590,885 3609,904 3669,904 3682.8,917.8 3682.8,997.8 3695,1010 3720,1010 3735,995 3735,920 3750,905 R76.2@3797.6,905
SLAVE: R6.1 U8.69 | length 2752.6
  Top Layer w7.87: U8.69@5917.32,4435.43 5955.43,4435.43 6206,4686 6556,4686 6664,4794 6969,4794 7004,4829 7004,5659 7109,5764 7464,5764 7490,5790 R6.1@7490,5922.6
SLAVE#: HDR4.10 R6.2 R20.2 | length 1173.8
  Top Layer w7.87: R20.2@7400,5562.6 7400,5525 7420,5505 7725,5505 7760,5540 7760,5965 7727.6,5997.4 R6.2@7490,5997.4 ; 7700,5505 HDR4.10@7700,5550
SLAVE_MODE: HDR4.6 U8.65 | length 2848.9
  Top Layer w7.87: U8.65@5917.32,4356.69 6061.69,4356.69 6151,4446 6416,4446 6700,4730 7010,4730 7068,4788 7068,5623 7145,5700 7650,5700 HDR4.6@7700,5750
SLAVE_TCK: HDR4.3 RA13.7 | length 2244.9
  Top Layer w7.87: RA13.7@6362,4600 6520,4600 6682,4762 6992,4762 7036,4806 7036,5641 7127,5732 7482,5732 HDR4.3@7600,5850
SLAVE_TCK#: RA13.2 U8.67 | length 405.2
  Top Layer w7.87: U8.67@5917.32,4396.06 5966.06,4396.06 6170,4600 RA13.2@6238,4600
SLAVE_TDI: HDR4.1 RA13.8 | length 2333
  Top Layer w7.87: RA13.8@6362,4650 6545,4650 6673,4778 6983,4778 7020,4815 7020,5650 7118,5748 7473,5748 7550,5825 7550,5940 7560,5950 HDR4.1@7600,5950
SLAVE_TDI#: RA13.1 U8.68 | length 417.7
  Top Layer w7.87: U8.68@5917.32,4415.75 5960.75,4415.75 6195,4650 RA13.1@6238,4650
SLAVE_TDO: HDR4.2 R21.2 U8.64 | length 3385.1
  Top Layer w7.87: U8.64@5917.32,4337.01 6067.01,4337.01 6160,4430 6425,4430 6708.42,4713.42 7018.42,4713.42 7084,4779 7084,5614 7154,5684 7526,5684 7550,5660 7550,5580 7532.6,5562.6 R21.2@7490,5562.6 ; 7550,5600 7720,5600 7744,5624 7744,5906 HDR4.2@7700,5950
SLAVE_TMS: HDR4.4 RA13.6 | length 2365.6
  Top Layer w7.87: RA13.6@6362,4550 6495,4550 6691,4746 7001,4746 7052,4797 7052,5632 7136,5716 7491,5716 7575,5800 7650,5800 HDR4.4@7700,5850
SLAVE_TMS#: RA13.3 U8.66 | length 392.6
  Top Layer w7.87: U8.66@5917.32,4376.38 5971.38,4376.38 6145,4550 RA13.3@6238,4550
SPARTAN_M0: JP3.1 R40.2 U8.35 | length 820.3
  Top Layer w7.87: U8.35@5824.8,3732.68 5824.8,3680.2 5860,3645 v1(5935,3645) ; R40.2@6152.4,4060 JP3.1@6250,4060
  Bottom Layer w7.87: v1(5935,3645) 6250,3960 JP3.1@6250,4060
SPI_CLK: J8.46 U8.12 | length 476.7
  Top Layer w7.87: J8.46@5371.26,3256.3 5371.26,3321.26 5372.05,3322.05 U8.12@5372.05,3732.68
SPI_DIN: J8.44 U8.11 | length 481.6
  Top Layer w7.87: J8.44@5339.76,3256.3 5339.76,3324.76 5352.36,3337.36 U8.11@5352.36,3732.68
SPI_DOUT: J8.50 U8.14 | length 485.8
  Top Layer w7.87: U8.14@5411.42,3732.68 5411.42,3348.58 5434.25,3325.75 J8.50@5434.25,3256.3
SPI_MODE: J8.52 U8.15 | length 490.7
  Top Layer w7.87: U8.15@5431.1,3732.68 5431.1,3353.9 5465.75,3319.25 J8.52@5465.75,3256.3
SPI_SEL: J8.48 U8.13 | length 480.9
  Top Layer w7.87: U8.13@5391.73,3732.68 5391.73,3343.27 5402.76,3332.24 J8.48@5402.76,3256.3
SPL1: RA14.1 U8.63 | length 344.6
  Top Layer w7.87: U8.63@5917.32,4317.32 6072.32,4317.32 6130,4375 RA14.1@6238,4375
SPL1#: LED9.1 RA14.8 | length 431.7
  Top Layer w7.87: RA14.8@6362,4375 6420,4375 6640,4595 LED9.1@6702.6,4595
SPL2: RA14.2 U8.60 | length 348.3
  Top Layer w7.87: U8.60@5917.32,4258.27 6138.27,4258.27 6205,4325 RA14.2@6238,4325
SPL2#: LED10.1 RA14.7 | length 411
  Top Layer w7.87: RA14.7@6362,4325 6420,4325 6590,4495 LED10.1@6702.6,4495
SPL3: RA14.3 U8.59 | length 335.8
  Top Layer w7.87: U8.59@5917.32,4238.58 6143.58,4238.58 6180,4275 RA14.3@6238,4275
SPL3#: LED11.1 RA14.6 | length 390.3
  Top Layer w7.87: RA14.6@6362,4275 6425,4275 6545,4395 LED11.1@6702.6,4395
SPL4: RA14.4 U8.58 | length 323.2
  Top Layer w7.87: U8.58@5917.32,4218.9 6148.9,4218.9 6155,4225 RA14.4@6238,4225
SPL4#: LED12.1 RA14.5 | length 369.6
  Top Layer w7.87: RA14.5@6362,4225 6430,4225 6500,4295 LED12.1@6702.6,4295
SPL5: RA15.1 U8.57 | length 517.8
  Top Layer w7.87: U8.57@5917.32,4199.21 6005.79,4199.21 6046,4159 6046,4034 6180,3900 RA15.1@6238,3900
SPL5#: LED13.1 RA15.8 | length 483.3
  Top Layer w7.87: RA15.8@6362,3900 6395,3900 6630,4135 6630,4170 6655,4195 LED13.1@6702.6,4195
SPL6: RA15.2 U8.56 | length 530.4
  Top Layer w7.87: U8.56@5917.32,4179.53 6000.47,4179.53 6030,4150 6030,4025 6205,3850 RA15.2@6238,3850
SPL6#: LED14.1 RA15.7 | length 442.1
  Top Layer w7.87: RA15.7@6362,3850 6395,3850 6640,4095 LED14.1@6702.6,4095
SPL7: RA15.3 U8.50 | length 443.6
  Top Layer w7.87: U8.50@5917.32,4061.42 5968.58,4061.42 6194,3836 6194,3811 6205,3800 RA15.3@6238,3800
SPL7#: LED15.1 RA15.6 | length 421.4
  Top Layer w7.87: RA15.6@6362,3800 6395,3800 6590,3995 LED15.1@6702.6,3995
SPL8: RA15.4 U8.49 | length 470.8
  Top Layer w7.87: U8.49@5917.32,4041.73 5963.27,4041.73 6178,3827 6178,3777 6205,3750 RA15.4@6238,3750
SPL8#: LED16.1 RA15.5 | length 400.7
  Top Layer w7.87: RA15.5@6362,3750 6395,3750 6540,3895 LED16.1@6702.6,3895
SW0: J9.44 RA21.1 S2.1 | length 2362.7
  Top Layer w7.87: J9.44@5339.76,1256.3 5339.76,1319.76 5630,1610 6545,1610 6599,1556 6936,1556 6965,1585 S2.1@7010,1585 7010,1680 6960,1730 6960,1910 6985,1935 7010,1935 7035,1960 RA21.1@7035,1993
SW1: J9.46 RA21.2 S2.2 | length 2396.7
  Top Layer w7.87: J9.46@5371.26,1256.3 5371.26,1321.26 5644,1594 6536,1594 6590,1540 7065,1540 S2.2@7110,1585 7110,1680 7060,1730 7060,1915 7085,1940 RA21.2@7085,1993
SW2: J9.48 RA21.3 S2.3 | length 2466.1
  Top Layer w7.87: J9.48@5402.76,1256.3 5402.76,1322.76 5658,1578 6527,1578 6581,1524 7149,1524 S2.3@7210,1585 7210,1680 7160,1730 7160,1915 7135,1940 RA21.3@7135,1993
SW3: J9.50 RA21.4 S2.4 | length 2570.9
  Top Layer w7.87: J9.50@5434.25,1256.3 5434.25,1324.25 5672,1562 6518,1562 6572,1508 7233,1508 S2.4@7310,1585 7310,1680 7260,1730 7260,1910 7235,1935 7210,1935 7185,1960 RA21.4@7185,1993
SW4: J9.52 RA22.1 S2.5 | length 2637.3
  Top Layer w7.87: J9.52@5465.75,1256.3 5465.75,1320.75 5691,1546 6509,1546 6563,1492 7317,1492 S2.5@7410,1585 7410,1680 7360,1730 7360,1910 7385,1935 7410,1935 7435,1960 RA22.1@7435,1993
SW5: J9.54 RA22.2 S2.6 | length 2671.3
  Top Layer w7.87: J9.54@5497.24,1256.3 5497.24,1322.24 5705,1530 6500,1530 6554,1476 7401,1476 S2.6@7510,1585 7510,1680 7460,1730 7460,1915 7485,1940 RA22.2@7485,1993
SW6: J9.56 RA22.3 S2.7 | length 2740.7
  Top Layer w7.87: J9.56@5528.74,1256.3 5528.74,1323.74 5719,1514 6491,1514 6545,1460 7485,1460 S2.7@7610,1585 7610,1680 7560,1730 7560,1915 7535,1940 RA22.3@7535,1993
SW7: J9.58 RA22.4 S2.8 | length 2845.5
  Top Layer w7.87: J9.58@5560.24,1256.3 5560.24,1325.24 5733,1498 6482,1498 6536,1444 7569,1444 S2.8@7710,1585 7710,1680 7660,1730 7660,1910 7635,1935 7610,1935 7585,1960 RA22.4@7585,1993
SWC0: J9.18 RA18.1 SW1.3 SW1.4 SW5.3 SW5.4 SW9.3 SW9.4 SW13.3 SW13.4 | length 8157.7
  Top Layer w7.87: SW13.3@835,1210 SW13.4@1115,1210 ; SW9.3@835,1660 SW9.4@1132.48,1660 ; SW5.3@835,2110 SW5.4@1115,2110 ; SW1.3@835,2560 SW1.4@1115,2560 ; v2(1120,3175) RA18.1@1120,3228 ; SW1.4@1132.48,2560 1132.48,2607.48 1192,2667 2538,2667 2634,2571 2634,1913 2663.75,1883.25 3770.65,1883.25 4189.65,1464.25 4837,1464.25 4930.31,1370.94 J9.18@4930.31,1256.3
  Bottom Layer w7.87: v2(890,1210) v2(890,2560) 1120,2790 v2(1120,3175)
  other v2: 890,1660 890,2110
SWC1: J9.16 RA18.2 SW2.3 SW2.4 SW6.3 SW6.4 SW10.3 SW10.4 SW14.3 SW14.4 | length 7669.8
  Top Layer w7.87: v2(1170,3175) RA18.2@1170,3228 ; SW14.3@1285,1210 SW14.4@1565,1210 ; SW10.3@1285,1660 SW10.4@1582.48,1660 ; SW6.3@1285,2110 SW6.4@1565,2110 ; SW2.3@1285,2560 SW2.4@1565,2560 ; SW2.4@1582.48,2560 1582.48,2607.48 1626,2651 2529,2651 2618.25,2561.75 2618.25,1905.75 2657,1867 3764.63,1867 4183.63,1448 4829.82,1448 4898.82,1379 J9.16@4898.82,1256.3
  Bottom Layer w7.87: v2(1170,3175) 1136,3141 1136,2764 v2(1340,2560) v2(1340,1210)
  other v2: 1340,1660 1340,2110
SWC2: J9.14 RA18.3 SW3.3 SW3.4 SW7.3 SW7.4 SW11.3 SW11.4 SW15.3 SW15.4 | length 7316
  Top Layer w7.87: v2(1220,3175) RA18.3@1220,3228 ; SW15.3@1735,1210 SW15.4@2015,1210 ; SW11.3@1735,1660 SW11.4@2032.48,1660 ; SW7.3@1735,2110 SW7.4@2015,2110 ; SW3.3@1735,2560 SW3.4@2015,2560 ; SW3.4@2032.48,2560 2032.48,2607.48 2060,2635 2520,2635 2601,2554 2601,1899 2648.75,1851.25 3758.1,1851.25 4177.1,1432.25 4821.07,1432.25 4867.32,1386 J9.14@4867.32,1256.3
  Bottom Layer w7.87: v2(1220,3175) 1790,2605 v2(1790,1210)
  other v2: 1790,1660 1790,2110 1790,2560
SWC3: J9.6 RA18.4 SW4.3 SW4.4 SW8.3 SW8.4 SW12.3 SW12.4 SW16.3 SW16.4 | length 6855.7
  Top Layer w7.87: v2(1270,3175) RA18.4@1270,3228 ; SW4.3@2167.13,2561.81 SW4.4@2482.48,2561.81 ; SW16.3@2185,1210 SW16.4@2465,1210 ; SW12.3@2185,1660 SW12.4@2465,1660 ; SW8.3@2185,2110 SW8.4@2465,2110 ; SW16.4@2482.48,1211.81 2583.81,1211.81 2641,1269 2641,1752 2674.5,1785.5 3734.77,1785.5 4154.27,1366 4733,1366 4741.34,1357.66 J9.6@4741.34,1256.3
  Bottom Layer w7.87: v2(1270,3175) 1270,3150 1860,2560 v2(2240,2560) v2(2240,1210)
  other v2: 2240,1660 2240,2110
SWR0: J9.20 SW1.1 SW1.2 SW2.1 SW2.2 SW3.1 SW3.2 SW4.1 SW4.2 | length 5228.3
  Top Layer w7.87: SW1.1@817.13,2738.58 2526.42,2738.58 2650,2615 2650,1920 2671,1899 3781.75,1899 4200.75,1480 4844.81,1480 4961.81,1363 J9.20@4961.81,1256.3
SWR1: J9.12 SW5.1 SW5.2 SW6.1 SW6.2 SW7.1 SW7.2 SW8.1 SW8.2 | length 4749.1
  Top Layer w7.87: SW5.1@817.13,2288.58 2565.42,2288.58 2585.25,2268.75 2585.25,1890.75 2642,1834 3753.08,1834 4171.08,1416 4815,1416 4835.83,1395.17 J9.12@4835.83,1256.3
